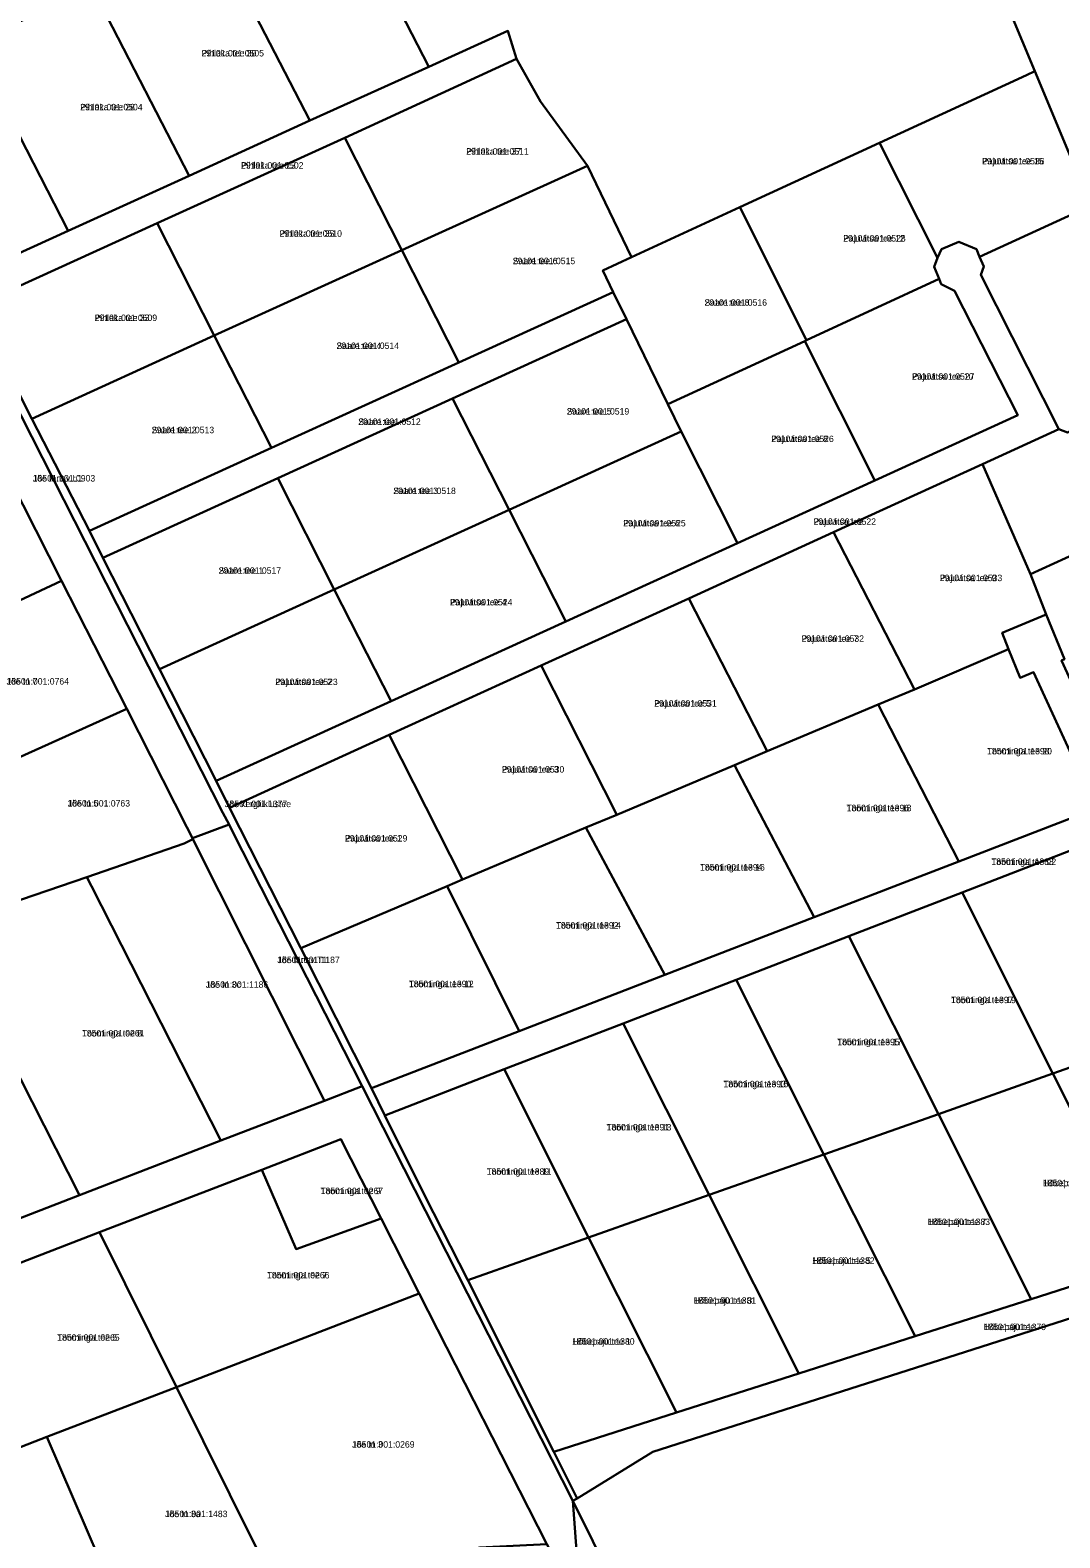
# Model space of a CAD drawing. Extents: x 660838 to 697091, y 6455678 to 6479886.
# Drawn here: x 663884.8 to 664124, y 6468601.6 to 6468951.8 of the extents above; entities that cross this region are included whole.
import ezdxf

# ---------------------------------------------------------------- set-up
doc = ezdxf.new("R2010")
doc.units = 0
for name, color, linetype in [('L_AADRESS', 7, 'Continuous'), ('PIIR', 7, 'Continuous'), ('TUNNUS', 7, 'Continuous')]:
    doc.layers.add(name, color=color, linetype=linetype)

msp = doc.modelspace()

# ---------------------------------------------------------------- linework, layer by layer
at = {"layer": 'PIIR'}
for points in [[(664260.89, 6468728.24), (664215.23, 6468709.47), (664203.34, 6468738), (664181.69, 6468789.93), (664169.9, 6468818.21), (664158.93, 6468844.48), (664148.69, 6468869.1), (664131.18, 6468911.08), (664118.18, 6468942.3), (664094.63, 6468998.74), (664093.92, 6469001.04), (664103.77, 6469005.34), (664107.11, 6469006.8), (664141.06, 6469021.65), (664266.53, 6469076.5), (664295.47, 6469089.15), (664296.36, 6469086.56), (664300.85, 6469048.07), (664302.86, 6469044.36), (664310.57, 6469047.99), (664311.87, 6469044.98), (664419.02, 6468792.9), (664365.27, 6468770.92), (664311.75, 6468749.04)], [(663982.18, 6468996.91), (664022.58, 6469014.49), (664071.5, 6469035.7), (664072.78, 6469032.57), (664081.25, 6469011.76), (664092.39, 6469004.63), (664092.79, 6469003.62), (664093.92, 6469001.04), (664094.63, 6468998.74), (664118.18, 6468942.3), (664116.19, 6468941.37), (664082.04, 6468925.58), (664049.64, 6468910.64), (664024.45, 6468899.03), (664014.22, 6468920.28), (664003.33, 6468935.24), (663997.73, 6468945.09), (663995.7, 6468951.62), (663977.4, 6468943.3), (663957.65, 6468981.7), (663955.7, 6468985.49), (663974.44, 6468993.57), (663978.5, 6468995.32)], [(663927.75, 6468973.43), (663934.35, 6468976.28), (663955.7, 6468985.49), (663957.65, 6468981.7), (663977.4, 6468943.3), (663949.78, 6468930.77), (663930.07, 6468968.93)], [(663899.39, 6468961.19), (663927.75, 6468973.43), (663930.07, 6468968.93), (663949.78, 6468930.77), (663921.69, 6468917.98), (663901.34, 6468957.42)], [(663871.12, 6468949), (663899.39, 6468961.19), (663901.34, 6468957.42), (663921.69, 6468917.98), (663893.65, 6468905.19), (663872.66, 6468945.99)], [(663977.4, 6468943.3), (663995.7, 6468951.62), (663997.73, 6468945.09), (663957.84, 6468926.75), (663914.3, 6468906.92), (663871.95, 6468887.65), (663868.76, 6468893.88), (663893.65, 6468905.19), (663921.69, 6468917.98), (663949.78, 6468930.77)], [(663846.26, 6468938.27), (663871.12, 6468949), (663872.66, 6468945.99), (663893.65, 6468905.19), (663868.76, 6468893.88), (663849.99, 6468930.8), (663847.49, 6468935.66)], [(663957.84, 6468926.75), (663997.73, 6468945.09), (664003.33, 6468935.24), (664014.22, 6468920.28), (663971.11, 6468900.68)], [(664116.19, 6468941.37), (664118.18, 6468942.3), (664131.18, 6468911.08), (664129.72, 6468910.38), (664105.31, 6468899.11), (664104.57, 6468900.91), (664100.52, 6468902.61), (664096.45, 6468900.93), (664095.57, 6468898.92), (664082.04, 6468925.58)], [(663839.78, 6468926.58), (663848.16, 6468930.06), (663929.57, 6468770.03), (663930.99, 6468767.26), (663922.49, 6468764.13), (663921.18, 6468766.64), (663907.21, 6468794.16), (663892.06, 6468823.9), (663877.12, 6468853.25), (663862.26, 6468882.43), (663858.13, 6468890.52)], [(663930.99, 6468767.26), (663929.57, 6468770.03), (663848.16, 6468930.06), (663849.99, 6468930.8), (663868.76, 6468893.88), (663871.95, 6468887.65), (663885.2, 6468861.54), (663898.53, 6468835.48), (663901.69, 6468829.23), (663914.85, 6468803.35), (663927.98, 6468777.46), (663931.12, 6468771.17), (663947.62, 6468738.59), (663964.06, 6468706.03), (663967.19, 6468699.73), (663976.47, 6468681.04), (663986.46, 6468661.45), (664006.4, 6468621.58), (664011.82, 6468610.76), (664010.85, 6468610.16), (663961.88, 6468706.49), (663931.96, 6468765.32)], [(663914.3, 6468906.92), (663957.84, 6468926.75), (663971.11, 6468900.68), (663927.56, 6468880.86)], [(664049.64, 6468910.64), (664082.04, 6468925.58), (664095.57, 6468898.92), (664094.78, 6468896.84), (664095.93, 6468894.02), (664065.11, 6468879.8)], [(663971.11, 6468900.68), (664014.22, 6468920.28), (664024.45, 6468899.03), (664017.83, 6468895.96), (664020.22, 6468890.96), (663984.37, 6468874.57)], [(664024.45, 6468899.03), (664049.64, 6468910.64), (664065.11, 6468879.8), (664064.71, 6468879.58), (664032.91, 6468864.91), (664023.27, 6468884.63), (664020.22, 6468890.96), (664017.83, 6468895.96)], [(664129.72, 6468910.38), (664131.18, 6468911.08), (664148.69, 6468869.1), (664147.4, 6468868.47), (664125.7, 6468858.36), (664123.7, 6468859.08), (664105.59, 6468894.95), (664106.26, 6468896.86), (664105.31, 6468899.11)], [(663871.95, 6468887.65), (663914.3, 6468906.92), (663927.56, 6468880.86), (663885.2, 6468861.54)], [(664095.57, 6468898.92), (664096.45, 6468900.93), (664100.52, 6468902.61), (664104.57, 6468900.91), (664105.31, 6468899.11), (664106.26, 6468896.86), (664105.59, 6468894.95), (664123.7, 6468859.08), (664106.02, 6468850.99), (664071.36, 6468835.17), (664037.75, 6468819.78), (664003.5, 6468804.21), (663968.17, 6468788.08), (663931.12, 6468771.17), (663927.98, 6468777.46), (663968.61, 6468795.97), (664009.19, 6468814.44), (664049.06, 6468832.65), (664080.95, 6468847.18), (664114.21, 6468862.38), (664099.5, 6468891.25), (664096.39, 6468892.79), (664095.93, 6468894.02), (664094.78, 6468896.84)], [(663927.56, 6468880.86), (663971.11, 6468900.68), (663984.37, 6468874.57), (663940.84, 6468854.79)], [(663984.37, 6468874.57), (664020.22, 6468890.96), (664023.27, 6468884.63), (663982.88, 6468866.2), (663942.28, 6468847.7), (663901.69, 6468829.23), (663898.53, 6468835.48), (663940.84, 6468854.79)], [(664065.11, 6468879.8), (664095.93, 6468894.02), (664096.39, 6468892.79), (664099.5, 6468891.25), (664114.21, 6468862.38), (664080.95, 6468847.18), (664064.71, 6468879.58)], [(663982.88, 6468866.2), (664023.27, 6468884.63), (664032.91, 6468864.91), (664036, 6468858.6), (663996.01, 6468840.37)], [(663885.2, 6468861.54), (663927.56, 6468880.86), (663940.84, 6468854.79), (663898.53, 6468835.48)], [(664032.91, 6468864.91), (664064.71, 6468879.58), (664080.95, 6468847.18), (664049.06, 6468832.65), (664036, 6468858.6)], [(664147.4, 6468868.47), (664148.69, 6468869.1), (664158.93, 6468844.48), (664157.82, 6468844), (664117.12, 6468825.46), (664106.02, 6468850.99), (664123.7, 6468859.08), (664125.7, 6468858.36)], [(663942.28, 6468847.7), (663982.88, 6468866.2), (663996.01, 6468840.37), (663955.42, 6468821.87)], [(663996.01, 6468840.37), (664036, 6468858.6), (664049.06, 6468832.65), (664009.19, 6468814.44)], [(663837.11, 6468834.72), (663877.12, 6468853.25), (663892.06, 6468823.9), (663851.67, 6468805.02), (663839.69, 6468829.46)], [(664071.36, 6468835.17), (664106.02, 6468850.99), (664117.12, 6468825.46), (664120.77, 6468816.05), (664110.56, 6468811.83), (664112, 6468808), (664090.17, 6468798.64)], [(663901.69, 6468829.23), (663942.28, 6468847.7), (663955.42, 6468821.87), (663914.85, 6468803.35)], [(664125.07, 6468805.66), (664120.77, 6468816.05), (664117.12, 6468825.46), (664157.82, 6468844), (664158.93, 6468844.48), (664169.9, 6468818.21), (664127.36, 6468798.79), (664124.35, 6468805.36)], [(663955.42, 6468821.87), (663996.01, 6468840.37), (664009.19, 6468814.44), (663968.61, 6468795.97)], [(664037.75, 6468819.78), (664071.36, 6468835.17), (664090.17, 6468798.64), (664081.76, 6468795.18), (664056, 6468784.29)], [(663851.67, 6468805.02), (663892.06, 6468823.9), (663907.21, 6468794.16), (663866.11, 6468775.67), (663859.39, 6468789.33)], [(663914.85, 6468803.35), (663955.42, 6468821.87), (663968.61, 6468795.97), (663927.98, 6468777.46)], [(664003.5, 6468804.21), (664037.75, 6468819.78), (664056, 6468784.29), (664048.41, 6468781.06), (664021.07, 6468769.54)], [(663967.19, 6468699.73), (663964.06, 6468706.03), (663998.36, 6468719.27), (664032.21, 6468732.35), (664066.87, 6468745.74), (664100.46, 6468758.71), (664132.37, 6468771.04), (664117.86, 6468802.66), (664114.73, 6468801.36), (664112, 6468808), (664110.56, 6468811.83), (664120.77, 6468816.05), (664125.07, 6468805.66), (664124.35, 6468805.36), (664127.36, 6468798.79), (664138.92, 6468773.57), (664150.6, 6468778.08), (664153.76, 6468771.79), (664127.47, 6468761.64), (664101.23, 6468751.5), (664074.98, 6468741.37), (664048.74, 6468731.23), (664022.5, 6468721.09), (663994.85, 6468710.42)], [(664100.46, 6468758.71), (664081.76, 6468795.18), (664090.17, 6468798.64), (664112, 6468808), (664114.73, 6468801.36), (664117.86, 6468802.66), (664132.37, 6468771.04)], [(663968.17, 6468788.08), (664003.5, 6468804.21), (664021.07, 6468769.54), (664013.88, 6468766.56), (663985.19, 6468754.49)], [(663878.17, 6468751.6), (663866.11, 6468775.67), (663907.21, 6468794.16), (663921.18, 6468766.64), (663922.49, 6468764.13), (663922.59, 6468763.86), (663920.56, 6468762.86), (663897.97, 6468755.08), (663879.62, 6468748.76)], [(664066.87, 6468745.74), (664048.41, 6468781.06), (664056, 6468784.29), (664081.76, 6468795.18), (664100.46, 6468758.71)], [(663931.12, 6468771.17), (663968.17, 6468788.08), (663985.19, 6468754.49), (663981.64, 6468752.96), (663947.62, 6468738.59)], [(664032.21, 6468732.35), (664013.88, 6468766.56), (664021.07, 6468769.54), (664048.41, 6468781.06), (664066.87, 6468745.74)], [(663922.59, 6468763.86), (663922.49, 6468764.13), (663930.99, 6468767.26), (663931.96, 6468765.32), (663961.88, 6468706.49), (663953.19, 6468703.12)], [(663998.36, 6468719.27), (663981.64, 6468752.96), (663985.19, 6468754.49), (664013.88, 6468766.56), (664032.21, 6468732.35)], [(663897.97, 6468755.08), (663920.56, 6468762.86), (663922.59, 6468763.86), (663953.19, 6468703.12), (663929.11, 6468693.85), (663899.05, 6468752.96)], [(664122.36, 6468709.42), (664101.23, 6468751.5), (664127.47, 6468761.64), (664148.97, 6468718.82)], [(663865.99, 6468740.73), (663864.55, 6468743.57), (663879.62, 6468748.76), (663897.97, 6468755.08), (663899.05, 6468752.96), (663929.11, 6468693.85), (663896.27, 6468681.19)], [(663964.06, 6468706.03), (663947.62, 6468738.59), (663981.64, 6468752.96), (663998.36, 6468719.27)], [(664095.74, 6468700.03), (664074.98, 6468741.37), (664101.23, 6468751.5), (664122.36, 6468709.42)], [(663863.44, 6468668.53), (663833.02, 6468728.32), (663831.25, 6468731.8), (663841.31, 6468735.57), (663844.94, 6468736.82), (663864.55, 6468743.57), (663865.99, 6468740.73), (663896.27, 6468681.19)], [(664069.13, 6468690.63), (664048.74, 6468731.23), (664074.98, 6468741.37), (664095.74, 6468700.03)], [(664042.51, 6468681.24), (664022.5, 6468721.09), (664048.74, 6468731.23), (664069.13, 6468690.63)], [(664014.47, 6468671.34), (663994.85, 6468710.42), (664022.5, 6468721.09), (664042.51, 6468681.24)], [(664144.32, 6468665.69), (664122.36, 6468709.42), (664148.97, 6468718.82), (664171.32, 6468674.33)], [(663976.47, 6468681.04), (663967.19, 6468699.73), (663994.85, 6468710.42), (664014.47, 6468671.34), (663986.46, 6468661.45)], [(664117.32, 6468657.06), (664095.74, 6468700.03), (664122.36, 6468709.42), (664144.32, 6468665.69)], [(663826, 6468643.72), (663820.81, 6468654.22), (663828.99, 6468657.82), (663831.18, 6468658.79), (663832.32, 6468656.54), (663863.44, 6468668.53), (663896.27, 6468681.19), (663929.11, 6468693.85), (663953.19, 6468703.12), (663961.88, 6468706.49), (664010.85, 6468610.16), (664011.97, 6468594.44), (664008.93, 6468591.97), (664004.79, 6468600.1), (663975.18, 6468658.35), (663966.33, 6468675.78), (663956.97, 6468694.2), (663938.59, 6468687.11), (663900.86, 6468672.57), (663863.38, 6468658.13)], [(664090.33, 6468648.43), (664069.13, 6468690.63), (664095.74, 6468700.03), (664117.32, 6468657.06)], [(663938.59, 6468687.11), (663956.97, 6468694.2), (663966.33, 6468675.78), (663946.54, 6468668.66)], [(664011.82, 6468610.76), (664006.4, 6468621.58), (664034.89, 6468630.69), (664063.33, 6468639.79), (664090.33, 6468648.43), (664117.32, 6468657.06), (664144.32, 6468665.69), (664171.32, 6468674.33), (664198.37, 6468682.98), (664207.81, 6468686), (664208.33, 6468687.24), (664212.4, 6468688.93), (664214.39, 6468688.1), (664216.46, 6468687.24), (664218.15, 6468683.18), (664216.46, 6468679.11), (664212.4, 6468677.43), (664208.84, 6468678.98), (664029.43, 6468621.6)], [(664063.33, 6468639.79), (664042.51, 6468681.24), (664069.13, 6468690.63), (664090.33, 6468648.43)], [(663900.86, 6468672.57), (663938.59, 6468687.11), (663946.54, 6468668.66), (663966.33, 6468675.78), (663975.18, 6468658.35), (663918.76, 6468636.59)], [(664034.89, 6468630.69), (664014.47, 6468671.34), (664042.51, 6468681.24), (664063.33, 6468639.79)], [(664156.44, 6468551.21), (664150.84, 6468549.63), (664113.09, 6468547.2), (664079.12, 6468545.02), (664052.46, 6468543.3), (664045.73, 6468542.87), (664045.52, 6468542.86), (664020.16, 6468591.48), (664010.85, 6468610.16), (664011.82, 6468610.76), (664029.43, 6468621.6), (664208.84, 6468678.98), (664257.87, 6468579.74), (664236.44, 6468573.71), (664197.17, 6468562.66)], [(663863.38, 6468658.13), (663900.86, 6468672.57), (663918.76, 6468636.59), (663888.66, 6468625.04), (663881.29, 6468622.19)], [(664006.4, 6468621.58), (663986.46, 6468661.45), (664014.47, 6468671.34), (664034.89, 6468630.69)], [(663918.76, 6468636.59), (663975.18, 6468658.35), (664004.79, 6468600.1), (663989.12, 6468599.37), (663964.17, 6468593.24), (663943.56, 6468586.75)], [(663943.56, 6468586.75), (663910.1, 6468575.16), (663888.66, 6468625.04), (663918.76, 6468636.59)], [(663816.98, 6468561.02), (663800.86, 6468591.18), (663843.84, 6468607.7), (663881.29, 6468622.19), (663888.66, 6468625.04), (663910.1, 6468575.16), (663943.56, 6468586.75), (663964.17, 6468593.24), (663989.12, 6468599.37), (664004.79, 6468600.1), (664008.93, 6468591.97), (664004.24, 6468594.14), (663995.43, 6468594.42), (663981.79, 6468592.26), (663962.02, 6468586.4), (663918.09, 6468572.36), (663869.44, 6468565.97), (663827.01, 6468555.9), (663824.66, 6468561.08), (663817.81, 6468559.34)], [(664011.97, 6468594.44), (664010.85, 6468610.16), (664020.16, 6468591.48), (664045.52, 6468542.86), (664069.8, 6468495.5), (664072.61, 6468490.03), (664083.83, 6468468.15), (664091.12, 6468453.52), (664095.38, 6468444.97), (664120.83, 6468393.91), (664157.25, 6468320.55), (664198.71, 6468241.32), (664192.29, 6468241.62), (664146.38, 6468329.37), (664096.86, 6468429.82), (664045.92, 6468529.46), (664044.65, 6468529.2), (664044.72, 6468533.87), (664017.4, 6468586.35)]]:
    msp.add_lwpolyline(points, close=True, dxfattribs=at)

# ---------------------------------------------------------------- texts
at = {"layer": 'L_AADRESS'}
for s, p in [('Pihlaka tee 30', (663924.59, 6468945.68)), ('Pihlaka tee 28', (663896.4, 6468933.17)), ('Pihlaka tee 37', (663986.07, 6468922.88)), ('Pihlaka tee L3', (663933.77, 6468919.63)), ('Pajuvitsa tee 15', (664105.89, 6468920.61)), ('Pihlaka tee 35', (663942.7, 6468903.8)), ('Pajuvitsa tee 12', (664073.64, 6468902.69)), ('Saare tee 6', (663996.88, 6468897.43)), ('Saare tee 8', (664041.43, 6468887.78)), ('Pihlaka tee 33', (663899.77, 6468884.23)), ('Saare tee 4', (663955.96, 6468877.74)), ('Pajuvitsa tee 10', (664089.62, 6468870.6)), ('Saare tee 5', (664009.43, 6468862.5)), ('Saare tee 2', (663913.02, 6468858.17)), ('Saare tee', (663961, 6468860.1)), ('Pajuvitsa tee 8', (664056.93, 6468856.11)), ('Jõe tänav L1', (663885.39, 6468846.95)), ('Saare tee 3', (663969.15, 6468844.04)), ('Pajuvitsa tee', (664066.75, 6468836.89)), ('Pajuvitsa tee 6', (664022.54, 6468836.52)), ('Saare tee 1', (663928.57, 6468825.53)), ('Pajuvitsa tee 9', (664096.07, 6468823.81)), ('Pajuvitsa tee 4', (663982.3, 6468818.17)), ('Pajuvitsa tee 7', (664063.96, 6468809.72)), ('Jõe tn 7', (663879.3, 6468799.79)), ('Pajuvitsa tee 2', (663941.72, 6468799.67)), ('Pajuvitsa tee 5', (664029.75, 6468794.67)), ('Toominga tee 20', (664107.06, 6468783.57)), ('Pajuvitsa tee 3', (663994.35, 6468779.35)), ('Jõe tn 5', (663893.48, 6468771.46)), ('Jõe kergliiklustee', (663929.99, 6468771.32)), ('Toominga tee 18', (664074.43, 6468770.37)), ('Pajuvitsa tee 1', (663957.9, 6468763.33)), ('Toominga tee 16', (664040.38, 6468756.59)), ('Toominga tee L2', (664108.05, 6468757.89)), ('Toominga tee 14', (664006.93, 6468743.11)), ('Jõe tänav T1', (663942.19, 6468735.09)), ('Jõe tn 3c', (663925.58, 6468729.36)), ('Toominga tee 12', (663972.75, 6468729.5)), ('Toominga tee 19', (664098.67, 6468725.79)), ('Toominga tee 8', (663896.83, 6468718.05)), ('Toominga tee 17', (664072.24, 6468716.02)), ('Toominga tee 15', (664045.82, 6468706.25)), ('Toominga tee 13', (664018.68, 6468696.22)), ('Toominga tee 11', (663990.83, 6468685.93)), ('Hõbepaju tee 9', (664120.03, 6468683.26)), ('Toominga tee 9', (663952.25, 6468681.43)), ('Hõbepaju tee 7', (664093.23, 6468674.25)), ('Hõbepaju tee 5', (664066.42, 6468665.23)), ('Toominga tee 7', (663939.8, 6468661.85)), ('Hõbepaju tee 3', (664038.9, 6468655.97)), ('Hõbepaju tee', (664106.25, 6468649.85)), ('Toominga tee 5', (663891.06, 6468647.38)), ('Hõbepaju tee 1', (664010.68, 6468646.47)), ('Jõe tn 3', (663959.56, 6468622.55)), ('Jõe tn 3a', (663916.11, 6468606.41))]:
    msp.add_text(s, height=1.5, dxfattribs=at).set_placement(p)
at = {"layer": 'TUNNUS'}
for s, p in [('29101:001:0505', (663924.59, 6468945.68)), ('29101:001:0504', (663896.4, 6468933.17)), ('29101:001:0511', (663986.07, 6468922.88)), ('29101:001:0502', (663933.77, 6468919.63)), ('29101:001:0536', (664105.89, 6468920.61)), ('29101:001:0510', (663942.7, 6468903.8)), ('29101:001:0528', (664073.64, 6468902.69)), ('29101:001:0515', (663996.88, 6468897.43)), ('29101:001:0516', (664041.43, 6468887.78)), ('29101:001:0509', (663899.77, 6468884.23)), ('29101:001:0514', (663955.96, 6468877.74)), ('29101:001:0527', (664089.62, 6468870.6)), ('29101:001:0519', (664009.43, 6468862.5)), ('29101:001:0513', (663913.02, 6468858.17)), ('29101:001:0512', (663961, 6468860.1)), ('29101:001:0526', (664056.93, 6468856.11)), ('18501:001:0903', (663885.39, 6468846.95)), ('29101:001:0518', (663969.15, 6468844.04)), ('29101:001:0522', (664066.75, 6468836.89)), ('29101:001:0525', (664022.54, 6468836.52)), ('29101:001:0517', (663928.57, 6468825.53)), ('29101:001:0533', (664096.07, 6468823.81)), ('29101:001:0524', (663982.3, 6468818.17)), ('29101:001:0532', (664063.96, 6468809.72)), ('18501:001:0764', (663879.3, 6468799.79)), ('29101:001:0523', (663941.72, 6468799.67)), ('29101:001:0531', (664029.75, 6468794.67)), ('18501:001:1398', (664107.06, 6468783.57)), ('29101:001:0530', (663994.35, 6468779.35)), ('18501:001:0763', (663893.48, 6468771.46)), ('18501:001:1377', (663929.99, 6468771.32)), ('18501:001:1396', (664074.43, 6468770.37)), ('29101:001:0529', (663957.9, 6468763.33)), ('18501:001:1394', (664040.38, 6468756.59)), ('18501:001:1388', (664108.05, 6468757.89)), ('18501:001:1392', (664006.93, 6468743.11)), ('18501:001:1187', (663942.19, 6468735.09)), ('18501:001:1186', (663925.58, 6468729.36)), ('18501:001:1390', (663972.75, 6468729.5)), ('18501:001:1397', (664098.67, 6468725.79)), ('18501:001:0261', (663896.83, 6468718.05)), ('18501:001:1395', (664072.24, 6468716.02)), ('18501:001:1393', (664045.82, 6468706.25)), ('18501:001:1391', (664018.68, 6468696.22)), ('18501:001:1389', (663990.83, 6468685.93)), ('18501:001:1384', (664120.03, 6468683.26)), ('18501:001:0267', (663952.25, 6468681.43)), ('18501:001:1383', (664093.23, 6468674.25)), ('18501:001:0266', (663939.8, 6468661.85)), ('18501:001:1382', (664066.42, 6468665.23)), ('18501:001:1381', (664038.9, 6468655.97)), ('18501:001:1379', (664106.25, 6468649.85)), ('18501:001:0265', (663891.06, 6468647.38)), ('18501:001:1380', (664010.68, 6468646.47)), ('18501:001:0269', (663959.56, 6468622.55)), ('18501:001:1483', (663916.11, 6468606.41))]:
    msp.add_text(s, height=1.5, dxfattribs=at).set_placement(p)

doc.saveas('drawing.dxf')
